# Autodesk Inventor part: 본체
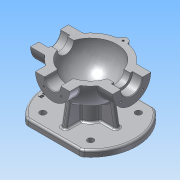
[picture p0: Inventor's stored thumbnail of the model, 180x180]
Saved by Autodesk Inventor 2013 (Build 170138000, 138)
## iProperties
Created: 2015-12
Part Number: 본체
Material: 알루미늄 6061
Document SubType Name: Modeling
Designer: mduedu
Density: 2.71 g/cm^3
Mass: 1035.31 g
Surface Area: 843.851 cm^2
Volume: 382.033 cm^3
Author: mduedu
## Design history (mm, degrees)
sketch "스케치1"
  geometry: L1 (-53, 0)-(53, 0); A1 r 53 centre (0, 0) between (53, 0) and (-53, 0); 2 further points
  constraints: 2 coincident, 2 end point, 2 point on circle, 1 centre point, 1 horizontal, 1 midpoint
  dimensions: "d0" = 53 radius of A1
revolve "회전1" sketch "스케치1" stored, may be unused: angle "d2" = 90 deg
feature "쉘1" dims "d11" = 10
node "작업 평면1"
sketch "스케치2"
  geometry: C1 r 31 at (0, 0); 1 further point
  constraints: 1 centre point, 1 coincident
  dimensions: "d4" = 62 diameter of C1
extrude "돌출1" join sketch "스케치2" stored distance "d5" = 10; taper "d6" = 0 deg
node "작업 평면2"
sketch "스케치3"
  geometry: C1 r 28 at (0, 0); 1 further point
  constraints: 1 centre point, 1 coincident
  dimensions: "d8" = 56 diameter of C1
extrude "돌출2" join sketch "스케치3" stored distance "d9" = 10; taper "d10" = 0 deg
hole "구멍1" diameter "d14" = 35; stored, may be unused: countersink angle "d18" = 90 deg, drill point angle "d20" = 0 deg; dims "d12" = 10, "d13" = 10, "d15" = 6, "d16" = 4, "d17" = 2, "d19" = 16
hole "구멍2" diameter "d23" = 27; stored, may be unused: countersink angle "d27" = 90 deg, drill point angle "d29" = 0 deg; dims "d21" = 10, "d22" = 10, "d24" = 6, "d25" = 4, "d26" = 2, "d28" = 16
fillet "모깎기1" dims "d30" = 0.3
hole "구멍3" diameter "d33" = 26; stored, may be unused: countersink angle "d37" = 90 deg, drill point angle "d39" = 0 deg; dims "d31" = 10, "d32" = 10, "d34" = 6, "d35" = 4, "d36" = 2, "d38" = 16
chamfer "모따기1" distance "d40" = 1; stored, may be unused: second distance "d41" = 2, angle "d42" = 45 deg
sketch "스케치4"
  geometry: L1 (0, 0)-(0, -25); L2 (0, 0)-(-17.678, -17.678); A1 r 25 centre (0, 0) between (-17.678, -17.678) and (0, -25); 1 further point
  constraints: 4 end point, 2 point on circle, 1 centre point, 1 coincident, 1 vertical
  dimensions: "d43" = 50 diameter of A1; "d47" = 45 deg angle of L1 L2
hole "구멍4" sketch "스케치4" at (-17.678, -17.678) diameter "d49" = 3.242; stored, may be unused: countersink angle "d53" = 90 deg, drill point angle "d55" = 118 deg; dims "d50" = 11, "d51" = 4, "d52" = 2, "d54" = 13
sketch "스케치5"
  geometry: L1 (0, 0)-(0, -20); L2 (0, 0)-(-14.142, -14.142); A1 r 20 centre (0, 0) between (0, -20) and (-14.142, -14.142); 2 further points
  constraints: 4 end point, 2 coincident, 2 point on circle, 1 centre point, 1 vertical
  dimensions: "d59" = 40 diameter of A1; "d65" = 45 deg angle of L1 L2
hole "구멍5" sketch "스케치5" at (-14.142, -14.142) diameter "d67" = 3.242; stored, may be unused: countersink angle "d71" = 90 deg, drill point angle "d73" = 118 deg; dims "d68" = 8, "d69" = 4, "d70" = 2, "d72" = 10
node "작업 평면3"
sketch "스케치6"
  geometry: C1 r 75 at (0, 0); 1 further point
  constraints: 1 centre point, 1 coincident
  dimensions: "d78" = 150 diameter of C1
extrude "돌출3" join sketch "스케치6" distance "d80" = 10; taper "d81" = 0 deg
sketch "스케치7"
  geometry: C1 r 20 at (0, 0); 1 further point
  constraints: 1 centre point, 1 coincident
  dimensions: "d82" = 40 diameter of C1
extrude "돌출4" join sketch "스케치7" stored distance "d84" = 10; taper "d85" = 0 deg
sketch "스케치8"
  geometry: 2 further points
  constraints: 1 coincident
hole "구멍6" sketch "스케치8" at (0, 0) diameter "d86" = 20; stored, may be unused: countersink angle "d90" = 90 deg, drill point angle "d92" = 118 deg; dims "d87" = 7, "d88" = 40, "d89" = 5, "d91" = 10
fillet "모깎기2" dims "d93" = 0.3
sketch "스케치9"
  geometry: L1 (75, -75)-(-75, -75) reference; L2 (-45, -75)-(-38.245, -36.692); A1 r 53 centre (0, 0) between (42.988, 31) and (42.988, -31) reference; 1 further point
  constraints: 2 end point, 1 point on circle, 1 point on line
  dimensions: "d94" = 45 horizontal distance of L2.start point (0, 0); "d95" = 80 deg angle of L2 L1
feature "리브1" sketch "스케치9" dims "d96" = 1, "d97" = 8, "d98" = 0, "d99" = 0, "d100" = 1, "d101" = 1
sketch "스케치14"
  geometry: L1 (-45, 110)-(45, 110); L2 (45, 110)-(45, 60); L3 (45, 60)-(-45, 60); L4 (-45, 60)-(-45, 110); L5 (-45, 110)-(45, 60); L6 (45, 110)-(-45, 60); L7 (-75, 0)-(75, 0); L8 (-45, -110)-(45, -110); L9 (45, -110)-(45, -60); L10 (45, -60)-(-45, -60); L11 (-45, -60)-(-45, -110); L12 (-45, -110)-(45, -60); L13 (45, -110)-(-45, -60); A1 r 75 centre (0, 0) between (45, 60) and (-45, 60) reference; 4 further points
  constraints: 26 end point, 5 midpoint, 5 symmetric about line, 4 point on circle, 2 parallel, 2 perpendicular, 1 coincident, 1 horizontal
  dimensions: "d151" = 15 distance edge to line of A1 L3; "d152" = 50 distance of L3.end L1.start
extrude "돌출7" cut sketch "스케치14" stored distance "d153" = 0; taper "d154" = 0 deg
fillet "모깎기9" dims "d155" = 10
sketch "스케치10"
  geometry: L1 (0, 0)-(0, -55); L2 (0, 0)-(-38.891, -38.891); A1 r 55 centre (0, 0) between (0, -55) and (-38.891, -38.891); 2 further points
  constraints: 4 end point, 2 coincident, 2 point on circle, 1 centre point, 1 vertical
  dimensions: "d105" = 110 diameter of A1; "d107" = 45 deg angle of L1 L2
hole "구멍7" sketch "스케치10" at (-38.891, -38.891) diameter "d109" = 10; stored, may be unused: countersink angle "d113" = 90 deg, drill point angle "d115" = 118 deg; dims "d110" = 7, "d111" = 40, "d112" = 5, "d114" = 10
fillet "모깎기3" dims "d120" = 3
fillet "모깎기4" dims "d121" = 3, "d122" = 3
fillet "모깎기5" dims "d123" = 3
fillet "모깎기6" dims "d124" = 3
sketch "스케치11"
  geometry: 2 further points
  constraints: 1 vertical alignment, 1 other
  dimensions: "d157" = 63 distance of point (0, 63) point (0, 0)
feature "엠보싱1" sketch "스케치11" dims "d125" = 0.5, "d126" = 0
sketch "스케치12"
  geometry: L1 (0, 100)-(0, -100); L2 (0, 100)-(100, 100); L3 (100, 100)-(100, -100); L4 (100, -100)-(0, -100); 2 further points
  constraints: 8 end point, 3 perpendicular, 1 coincident, 1 midpoint, 1 vertical
  dimensions: "d127" = 200 distance of L2.end L3.end; "d129" = 100 distance between parallel lines of L1 L3
extrude "돌출5" cut sketch "스케치12" stored distance "d130" = 10; taper "d131" = 0 deg
sketch "스케치13"
  geometry: C1 r 7 at (0, 53); A1 r 53 centre (0, 0) between (42.113, 32.179) and (-42.113, 32.179) reference; 1 further point
  constraints: 1 centre point, 1 point on circle
  dimensions: "d132" = 14 diameter of C1
extrude "돌출6" join sketch "스케치13" distance "d134" = 15; taper "d135" = 0 deg; dims "d29" = 0
hole "구멍8" diameter "d139" = 3.242; stored, may be unused: countersink angle "d143" = 90 deg, drill point angle "d145" = 118 deg; dims "d140" = 8, "d141" = 4, "d142" = 2, "d144" = 10, "d148" = 10, "d149" = 10
fillet "모깎기7" dims "d146" = 3
fillet "모깎기8" dims "d147" = 3
node "솔리드1"
mirror "대칭1"
mirror "대칭2"
pattern_circular "원형 패턴1" dims angle "d57" = 360 deg
mirror "대칭3"
pattern_circular "원형 패턴2" dims angle "d75" = 360 deg
pattern_circular "원형 패턴3" dims angle "d103" = 360 deg
pattern_circular "원형 패턴4" dims angle "d118" = 360 deg
other parameters: "d3" = 67, "d7" = 62, "d77" = -85
